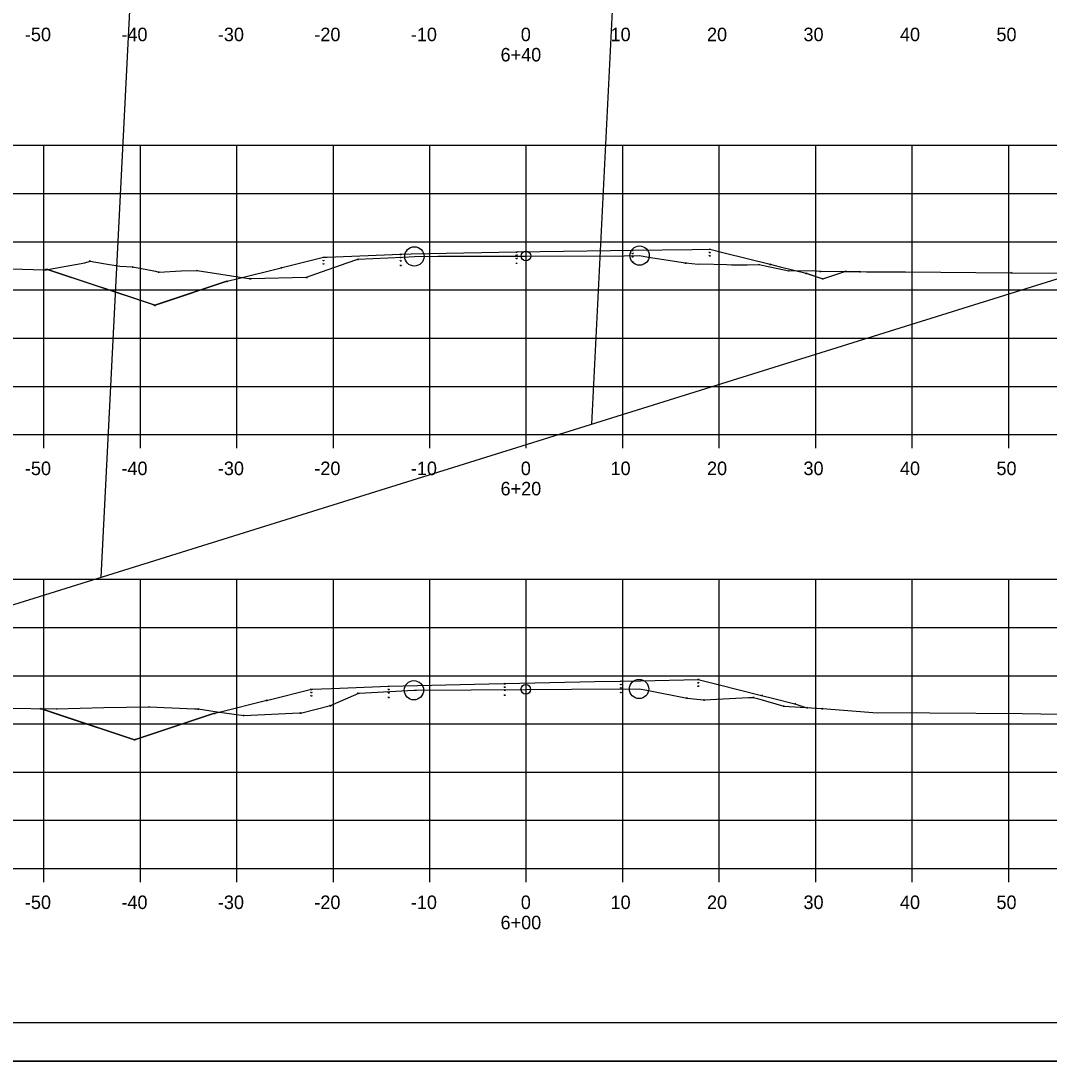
# Model space of a CAD drawing. Extents: x 1300404 to 1323571, y 234004 to 252077.
# Drawn here: x 1315664.9 to 1315771.5, y 242128.5 to 242236.4 of the extents above; entities that cross this region are included whole.
import ezdxf

# ---------------------------------------------------------------- set-up
doc = ezdxf.new("R2010")
doc.units = 0
for name, color, linetype in [('Default', 7, 'Continuous'), ('R_Axis', 7, 'Continuous'), ('R_Axis Annot', 7, 'Continuous'), ('R_Draft', 7, 'Continuous'), ('R_Exist Surface', 7, 'Continuous'), ('R_Fin Surface', 7, 'Continuous'), ('R_Floodway', 7, 'Continuous'), ('R_Grid', 7, 'Continuous'), ('R_No Plot', 7, 'Continuous')]:
    doc.layers.add(name, color=color, linetype=linetype)

msp = doc.modelspace()

# ---------------------------------------------------------------- linework, layer by layer
at = {"layer": 'Default'}
msp.add_line((1315875.46, 242132.44), (1315559.28, 242132.44), dxfattribs=at)
at = {"layer": 'R_Axis'}
for p, q in [((1315577.28, 242193.44), (1315857.28, 242193.44)), ((1315667.28, 242192.04), (1315667.28, 242193.44)), ((1315677.28, 242192.04), (1315677.28, 242193.44)), ((1315687.28, 242192.04), (1315687.28, 242193.44)), ((1315697.28, 242192.04), (1315697.28, 242193.44)), ((1315707.28, 242192.04), (1315707.28, 242193.44)), ((1315717.28, 242192.04), (1315717.28, 242193.44)), ((1315727.28, 242192.04), (1315727.28, 242193.44)), ((1315737.28, 242192.04), (1315737.28, 242193.44)), ((1315747.28, 242192.04), (1315747.28, 242193.44)), ((1315757.28, 242192.04), (1315757.28, 242193.44)), ((1315767.28, 242192.04), (1315767.28, 242193.44)), ((1315577.28, 242148.44), (1315857.28, 242148.44)), ((1315667.28, 242147.04), (1315667.28, 242148.44)), ((1315677.28, 242147.04), (1315677.28, 242148.44)), ((1315687.28, 242147.04), (1315687.28, 242148.44)), ((1315697.28, 242147.04), (1315697.28, 242148.44)), ((1315707.28, 242147.04), (1315707.28, 242148.44)), ((1315717.28, 242147.04), (1315717.28, 242148.44)), ((1315727.28, 242147.04), (1315727.28, 242148.44)), ((1315737.28, 242147.04), (1315737.28, 242148.44)), ((1315747.28, 242147.04), (1315747.28, 242148.44)), ((1315757.28, 242147.04), (1315757.28, 242148.44)), ((1315767.28, 242147.04), (1315767.28, 242148.44))]:
    msp.add_line(p, q, dxfattribs=at)
at = {"layer": 'R_Draft'}
for points in [[(1315704.27, 242212.2), (1315704.32, 242212.1), (1315704.22, 242212.1)], [(1315716.28, 242212.44), (1315716.33, 242212.34), (1315716.23, 242212.34)], [(1315716.28, 242212.11), (1315716.33, 242212.01), (1315716.23, 242212.01)], [(1315728.29, 242212.61), (1315728.34, 242212.51), (1315728.24, 242212.51)], [(1315728.29, 242212.28), (1315728.34, 242212.18), (1315728.24, 242212.18)], [(1315736.3, 242212.72), (1315736.35, 242212.62), (1315736.25, 242212.62)], [(1315736.3, 242212.39), (1315736.35, 242212.29), (1315736.25, 242212.29)], [(1315672.06, 242211.49), (1315672.11, 242211.39), (1315672.01, 242211.39)], [(1315696.26, 242211.89), (1315696.31, 242211.79), (1315696.21, 242211.79)], [(1315696.26, 242211.55), (1315696.31, 242211.45), (1315696.21, 242211.45)], [(1315696.26, 242211.22), (1315696.31, 242211.12), (1315696.21, 242211.12)], [(1315699.82, 242211.68), (1315699.87, 242211.58), (1315699.77, 242211.58)], [(1315704.27, 242211.87), (1315704.32, 242211.77), (1315704.22, 242211.77)], [(1315704.27, 242211.54), (1315704.32, 242211.44), (1315704.22, 242211.44)], [(1315704.27, 242211.04), (1315704.32, 242210.94), (1315704.22, 242210.94)], [(1315716.28, 242211.78), (1315716.33, 242211.68), (1315716.23, 242211.68)], [(1315716.28, 242211.27), (1315716.33, 242211.17), (1315716.23, 242211.17)], [(1315728.29, 242211.95), (1315728.34, 242211.85), (1315728.24, 242211.85)], [(1315728.29, 242211.44), (1315728.34, 242211.34), (1315728.24, 242211.34)], [(1315733.79, 242211.29), (1315733.84, 242211.19), (1315733.74, 242211.19)], [(1315736.3, 242212.06), (1315736.35, 242211.96), (1315736.25, 242211.96)], [(1315741.41, 242211.13), (1315741.46, 242211.03), (1315741.36, 242211.03)], [(1315742.57, 242211.15), (1315742.62, 242211.05), (1315742.52, 242211.05)], [(1315667.51, 242210.58), (1315667.56, 242210.48), (1315667.46, 242210.48)], [(1315667.55, 242210.64), (1315667.6, 242210.54), (1315667.5, 242210.54)], [(1315667.55, 242210.64), (1315667.6, 242210.54), (1315667.5, 242210.54)], [(1315676.48, 242210.88), (1315676.53, 242210.78), (1315676.43, 242210.78)], [(1315679.18, 242210.34), (1315679.23, 242210.24), (1315679.13, 242210.24)], [(1315683.15, 242210.51), (1315683.2, 242210.41), (1315683.1, 242210.41)], [(1315691.88, 242210.79), (1315691.93, 242210.69), (1315691.83, 242210.69)], [(1315744.49, 242210.48), (1315744.54, 242210.38), (1315744.44, 242210.38)], [(1315746.3, 242210.22), (1315746.35, 242210.12), (1315746.25, 242210.12)], [(1315747.76, 242210.43), (1315747.81, 242210.33), (1315747.71, 242210.33)], [(1315750.39, 242210.44), (1315750.44, 242210.34), (1315750.34, 242210.34)], [(1315750.39, 242210.44), (1315750.44, 242210.34), (1315750.34, 242210.34)], [(1315751.87, 242210.4), (1315751.92, 242210.3), (1315751.82, 242210.3)], [(1315767.55, 242210.28), (1315767.6, 242210.18), (1315767.5, 242210.18)], [(1315686.25, 242209.39), (1315686.3, 242209.29), (1315686.2, 242209.29)], [(1315688.69, 242209.67), (1315688.74, 242209.57), (1315688.64, 242209.57)], [(1315694.5, 242209.81), (1315694.55, 242209.71), (1315694.45, 242209.71)], [(1315748.01, 242209.65), (1315748.06, 242209.55), (1315747.96, 242209.55)], [(1315678.79, 242206.91), (1315678.84, 242206.81), (1315678.74, 242206.81)], [(1315727.08, 242167.93), (1315727.13, 242167.83), (1315727.03, 242167.83)], [(1315735.1, 242168.1), (1315735.15, 242168), (1315735.05, 242168)], [(1315695, 242167.08), (1315695.05, 242166.98), (1315694.95, 242166.98)], [(1315703.02, 242167.4), (1315703.07, 242167.3), (1315702.97, 242167.3)], [(1315703.02, 242167.06), (1315703.07, 242166.96), (1315702.97, 242166.96)], [(1315715.05, 242167.67), (1315715.1, 242167.57), (1315715, 242167.57)], [(1315715.05, 242167.33), (1315715.1, 242167.23), (1315715, 242167.23)], [(1315715.05, 242167), (1315715.1, 242166.9), (1315715, 242166.9)], [(1315727.08, 242167.59), (1315727.13, 242167.49), (1315727.03, 242167.49)], [(1315727.08, 242167.26), (1315727.13, 242167.16), (1315727.03, 242167.16)], [(1315727.08, 242166.76), (1315727.13, 242166.66), (1315727.03, 242166.66)], [(1315735.1, 242167.76), (1315735.15, 242167.66), (1315735.05, 242167.66)], [(1315735.1, 242167.43), (1315735.15, 242167.33), (1315735.05, 242167.33)], [(1315690.38, 242165.94), (1315690.43, 242165.84), (1315690.33, 242165.84)], [(1315695, 242166.75), (1315695.05, 242166.65), (1315694.95, 242166.65)], [(1315695, 242166.42), (1315695.05, 242166.32), (1315694.95, 242166.32)], [(1315699.84, 242166.66), (1315699.89, 242166.56), (1315699.79, 242166.56)], [(1315703.02, 242166.73), (1315703.07, 242166.63), (1315702.97, 242166.63)], [(1315703.02, 242166.23), (1315703.07, 242166.13), (1315702.97, 242166.13)], [(1315715.05, 242166.5), (1315715.1, 242166.4), (1315715, 242166.4)], [(1315733.94, 242166.17), (1315733.99, 242166.07), (1315733.89, 242166.07)], [(1315735.71, 242165.98), (1315735.76, 242165.88), (1315735.66, 242165.88)], [(1315740.8, 242166.23), (1315740.85, 242166.13), (1315740.75, 242166.13)], [(1315741.67, 242166.45), (1315741.72, 242166.35), (1315741.62, 242166.35)], [(1315666.94, 242165.07), (1315666.99, 242164.97), (1315666.89, 242164.97)], [(1315666.94, 242165.07), (1315666.99, 242164.97), (1315666.89, 242164.97)], [(1315668.59, 242165.05), (1315668.64, 242164.95), (1315668.54, 242164.95)], [(1315678.19, 242165.27), (1315678.24, 242165.17), (1315678.14, 242165.17)], [(1315683.28, 242165.04), (1315683.33, 242164.94), (1315683.23, 242164.94)], [(1315693.9, 242164.63), (1315693.95, 242164.53), (1315693.85, 242164.53)], [(1315696.98, 242165.39), (1315697.03, 242165.29), (1315696.93, 242165.29)], [(1315743.97, 242165.33), (1315744.02, 242165.23), (1315743.92, 242165.23)], [(1315745.12, 242165.58), (1315745.17, 242165.48), (1315745.07, 242165.48)], [(1315746.37, 242165.16), (1315746.42, 242165.06), (1315746.32, 242165.06)], [(1315746.37, 242165.16), (1315746.42, 242165.06), (1315746.32, 242165.06)], [(1315747.96, 242165.08), (1315748.01, 242164.98), (1315747.91, 242164.98)], [(1315684.96, 242164.59), (1315685.01, 242164.49), (1315684.91, 242164.49)], [(1315687.99, 242164.37), (1315688.04, 242164.27), (1315687.94, 242164.27)], [(1315676.68, 242161.85), (1315676.73, 242161.75), (1315676.63, 242161.75)]]:
    msp.add_lwpolyline(points, close=True, dxfattribs=at)
at = {"layer": 'R_Exist Surface'}
for points in [[(1315655.1, 242210.9), (1315667.26, 242210.52), (1315667.51, 242210.53), (1315668.62, 242210.75), (1315671.51, 242211.27), (1315672.06, 242211.44), (1315673.47, 242211.18), (1315675.14, 242210.91), (1315676.48, 242210.83), (1315678.86, 242210.39), (1315679.18, 242210.29), (1315681.51, 242210.43), (1315683.15, 242210.46), (1315688.51, 242209.64), (1315688.69, 242209.62), (1315688.74, 242209.62), (1315694.5, 242209.76), (1315695.48, 242210.11), (1315698.71, 242211.25), (1315699.82, 242211.63), (1315704.48, 242211.85), (1315705.68, 242211.92), (1315708.12, 242211.93), (1315717.24, 242211.96), (1315727.42, 242211.99), (1315729.02, 242212), (1315729.95, 242211.83), (1315733.79, 242211.24), (1315735.1, 242211.13), (1315735.35, 242211.16), (1315738.05, 242211.09), (1315738.54, 242211.04), (1315740.17, 242211.04), (1315741.41, 242211.08), (1315742.04, 242210.94), (1315744.49, 242210.43), (1315746.93, 242210.45), (1315747.76, 242210.38), (1315750.19, 242210.37), (1315751.87, 242210.35), (1315752.53, 242210.32), (1315756.6, 242210.32), (1315767.55, 242210.23), (1315772.47, 242210.19)], [(1315657.98, 242165.13), (1315668.59, 242165), (1315673.48, 242165.13), (1315678.19, 242165.22), (1315682.9, 242164.99), (1315683.28, 242164.99), (1315685.23, 242164.7), (1315687.99, 242164.32), (1315693.76, 242164.58), (1315693.9, 242164.58), (1315694.03, 242164.6), (1315696.98, 242165.34), (1315699.61, 242166.49), (1315699.84, 242166.61), (1315700, 242166.62), (1315705.63, 242166.93), (1315705.91, 242166.94), (1315717.23, 242167.02), (1315721.95, 242167.04), (1315728.97, 242167.06), (1315729.78, 242166.92), (1315733.94, 242166.12), (1315734.96, 242166), (1315735.71, 242165.93), (1315740.31, 242166.17), (1315740.8, 242166.18), (1315741.24, 242166.08), (1315743.97, 242165.28), (1315747.96, 242165.03), (1315747.96, 242165.03), (1315747.97, 242165.03), (1315747.97, 242165.03), (1315753.65, 242164.59), (1315757.74, 242164.62), (1315759.11, 242164.6), (1315768.68, 242164.53), (1315776.42, 242164.39)]]:
    msp.add_lwpolyline(points, dxfattribs=at)
at = {"layer": 'R_Fin Surface'}
for points in [[(1315667.55, 242210.59), (1315678.31, 242207.02), (1315678.79, 242206.86), (1315679.12, 242206.97), (1315686.25, 242209.34), (1315686.28, 242209.35), (1315687.4, 242209.63), (1315691.75, 242210.71), (1315691.88, 242210.74), (1315691.98, 242210.77), (1315696.26, 242211.84), (1315696.63, 242211.85), (1315704.27, 242212.15), (1315705.33, 242212.17), (1315716.28, 242212.39), (1315726, 242212.54), (1315728.29, 242212.56), (1315734.46, 242212.65), (1315736.3, 242212.67), (1315737.78, 242212.3), (1315742.57, 242211.1), (1315743.6, 242210.84), (1315746.3, 242210.17), (1315746.76, 242210.01), (1315748.01, 242209.6), (1315749.46, 242210.08), (1315750.39, 242210.39)], [(1315666.94, 242165.02), (1315669.06, 242164.31), (1315676.68, 242161.8), (1315678.01, 242162.24), (1315684.96, 242164.54), (1315685.44, 242164.66), (1315690.38, 242165.89), (1315690.62, 242165.95), (1315695, 242167.03), (1315697.08, 242167.11), (1315703.02, 242167.35), (1315713.41, 242167.58), (1315715.05, 242167.62), (1315724.38, 242167.83), (1315727.08, 242167.88), (1315729.13, 242167.92), (1315735.1, 242168.05), (1315737.16, 242167.53), (1315741.67, 242166.4), (1315742.95, 242166.08), (1315745.12, 242165.53), (1315745.22, 242165.5), (1315746.37, 242165.11)]]:
    msp.add_lwpolyline(points, dxfattribs=at)
at = {"layer": 'R_Floodway'}
for p, q in [((1315724.08, 242194.52), (1315766.53, 243041.85)), ((1315673.23, 242178.64), (1315715.45, 243021.54))]:
    msp.add_line(p, q, dxfattribs=at)
msp.add_lwpolyline([(1317712.51, 244123.58), (1317619.12, 244094.42), (1317572.79, 244038.68), (1317546.01, 243986.8), (1317536.96, 243950.96), (1317518.15, 243864.8), (1317504.76, 243838.86), (1317478.47, 243796.63), (1317454.94, 243761.52), (1317297.11, 243701.73), (1317174.77, 243577.23), (1317137.14, 243501.7), (1317099.26, 243421.34), (1317083.47, 243347.13), (1317140.59, 243085.36), (1317061.58, 242907.87), (1316926.82, 242776.74), (1316838.38, 242701.35), (1316633.63, 242525.36), (1316510.92, 242442.01), (1316282.26, 242368.85), (1315441.7, 242106.33), (1315147.76, 242034.03), (1314832.32, 242016.05)], dxfattribs=at)
at = {"layer": 'R_Grid'}
for p, q in [((1315577.28, 242223.44), (1315857.28, 242223.44)), ((1315667.28, 242193.44), (1315667.28, 242223.44)), ((1315677.28, 242193.44), (1315677.28, 242223.44)), ((1315687.28, 242193.44), (1315687.28, 242223.44)), ((1315697.28, 242193.44), (1315697.28, 242223.44)), ((1315707.28, 242193.44), (1315707.28, 242223.44)), ((1315717.28, 242193.44), (1315717.28, 242223.44)), ((1315727.28, 242193.44), (1315727.28, 242223.44)), ((1315737.28, 242193.44), (1315737.28, 242223.44)), ((1315747.28, 242193.44), (1315747.28, 242223.44)), ((1315757.28, 242193.44), (1315757.28, 242223.44)), ((1315767.28, 242193.44), (1315767.28, 242223.44)), ((1315577.28, 242218.44), (1315857.28, 242218.44)), ((1315577.28, 242213.44), (1315857.28, 242213.44)), ((1315577.28, 242208.44), (1315857.28, 242208.44)), ((1315577.28, 242203.44), (1315857.28, 242203.44)), ((1315577.28, 242198.44), (1315857.28, 242198.44)), ((1315577.28, 242193.44), (1315857.28, 242193.44)), ((1315577.28, 242178.44), (1315857.28, 242178.44)), ((1315667.28, 242148.44), (1315667.28, 242178.44)), ((1315677.28, 242148.44), (1315677.28, 242178.44)), ((1315687.28, 242148.44), (1315687.28, 242178.44)), ((1315697.28, 242148.44), (1315697.28, 242178.44)), ((1315707.28, 242148.44), (1315707.28, 242178.44)), ((1315717.28, 242148.44), (1315717.28, 242178.44)), ((1315727.28, 242148.44), (1315727.28, 242178.44)), ((1315737.28, 242148.44), (1315737.28, 242178.44)), ((1315747.28, 242148.44), (1315747.28, 242178.44)), ((1315757.28, 242148.44), (1315757.28, 242178.44)), ((1315767.28, 242148.44), (1315767.28, 242178.44)), ((1315577.28, 242173.44), (1315857.28, 242173.44)), ((1315577.28, 242168.44), (1315857.28, 242168.44)), ((1315577.28, 242163.44), (1315857.28, 242163.44)), ((1315577.28, 242158.44), (1315857.28, 242158.44)), ((1315577.28, 242153.44), (1315857.28, 242153.44)), ((1315577.28, 242148.44), (1315857.28, 242148.44))]:
    msp.add_line(p, q, dxfattribs=at)
at = {"layer": 'R_No Plot'}
msp.add_line((1315546.87, 242128.46), (1315880.21, 242128.46), dxfattribs=at)
for points in [[(1315546.87, 242341.8), (1315880.21, 242341.8), (1315880.21, 242128.46), (1315546.87, 242128.46)], [(1315793.2, 242337.9), (1315793.2, 242328.02), (1315828.93, 242328.02), (1315828.93, 242325.1), (1315852.13, 242325.1), (1315852.13, 242302.98), (1315875.46, 242302.98), (1315875.46, 242132.44), (1315559.28, 242132.44), (1315559.28, 242337.9)]]:
    msp.add_lwpolyline(points, close=True, dxfattribs=at)
for points in [[(1315678.79, 242206.86), (1315667.55, 242210.59)], [(1315686.25, 242209.34), (1315678.79, 242206.86), (1315667.55, 242210.59)], [(1315686.25, 242209.34), (1315678.79, 242206.86), (1315667.55, 242210.59)], [(1315686.25, 242209.34), (1315678.79, 242206.86), (1315667.55, 242210.59)], [(1315686.25, 242209.34), (1315678.79, 242206.86), (1315667.55, 242210.59)], [(1315686.25, 242209.34), (1315678.79, 242206.86), (1315667.55, 242210.59)], [(1315746.3, 242210.17), (1315748.01, 242209.6), (1315750.39, 242210.39)], [(1315746.3, 242210.17), (1315748.01, 242209.6), (1315750.39, 242210.39)], [(1315746.3, 242210.17), (1315748.01, 242209.6), (1315750.39, 242210.39)], [(1315746.3, 242210.17), (1315748.01, 242209.6), (1315750.39, 242210.39)], [(1315676.68, 242161.8), (1315666.94, 242165.02)], [(1315684.96, 242164.54), (1315676.68, 242161.8), (1315666.94, 242165.02)], [(1315684.96, 242164.54), (1315676.68, 242161.8), (1315666.94, 242165.02)], [(1315684.96, 242164.54), (1315676.68, 242161.8), (1315666.94, 242165.02)], [(1315684.96, 242164.54), (1315676.68, 242161.8), (1315666.94, 242165.02)], [(1315684.96, 242164.54), (1315676.68, 242161.8), (1315666.94, 242165.02)]]:
    msp.add_lwpolyline(points, dxfattribs=at)
for centre, radius in [((1315705.68, 242211.92), 1), ((1315717.24, 242211.96), 0.5), ((1315729.02, 242212), 1), ((1315705.63, 242166.93), 1), ((1315728.97, 242167.06), 1), ((1315717.23, 242167.02), 0.5)]:
    msp.add_circle(centre, radius, dxfattribs=at)

# ---------------------------------------------------------------- texts
at = {"layer": 'R_Axis Annot'}
for s, p in [('-50', (1315665.31, 242234.24)), ('-40', (1315675.31, 242234.24)), ('-30', (1315685.31, 242234.24)), ('-20', (1315695.31, 242234.24)), ('-10', (1315705.31, 242234.24)), ('0', (1315716.71, 242234.24)), ('10', (1315726.01, 242234.24)), ('20', (1315736.01, 242234.24)), ('30', (1315746.01, 242234.24)), ('40', (1315756.01, 242234.24)), ('50', (1315766.01, 242234.24)), ('6+40', (1315714.61, 242232.14)), ('-50', (1315665.31, 242189.24)), ('-40', (1315675.31, 242189.24)), ('-30', (1315685.31, 242189.24)), ('-20', (1315695.31, 242189.24)), ('-10', (1315705.31, 242189.24)), ('0', (1315716.71, 242189.24)), ('10', (1315726.01, 242189.24)), ('20', (1315736.01, 242189.24)), ('30', (1315746.01, 242189.24)), ('40', (1315756.01, 242189.24)), ('50', (1315766.01, 242189.24)), ('6+20', (1315714.61, 242187.14)), ('-50', (1315665.31, 242144.24)), ('-40', (1315675.31, 242144.24)), ('-30', (1315685.31, 242144.24)), ('-20', (1315695.31, 242144.24)), ('-10', (1315705.31, 242144.24)), ('0', (1315716.71, 242144.24)), ('10', (1315726.01, 242144.24)), ('20', (1315736.01, 242144.24)), ('30', (1315746.01, 242144.24)), ('40', (1315756.01, 242144.24)), ('50', (1315766.01, 242144.24)), ('6+00', (1315714.61, 242142.14))]:
    msp.add_text(s, height=1.4, dxfattribs=at).set_placement(p)

doc.saveas('drawing.dxf')
